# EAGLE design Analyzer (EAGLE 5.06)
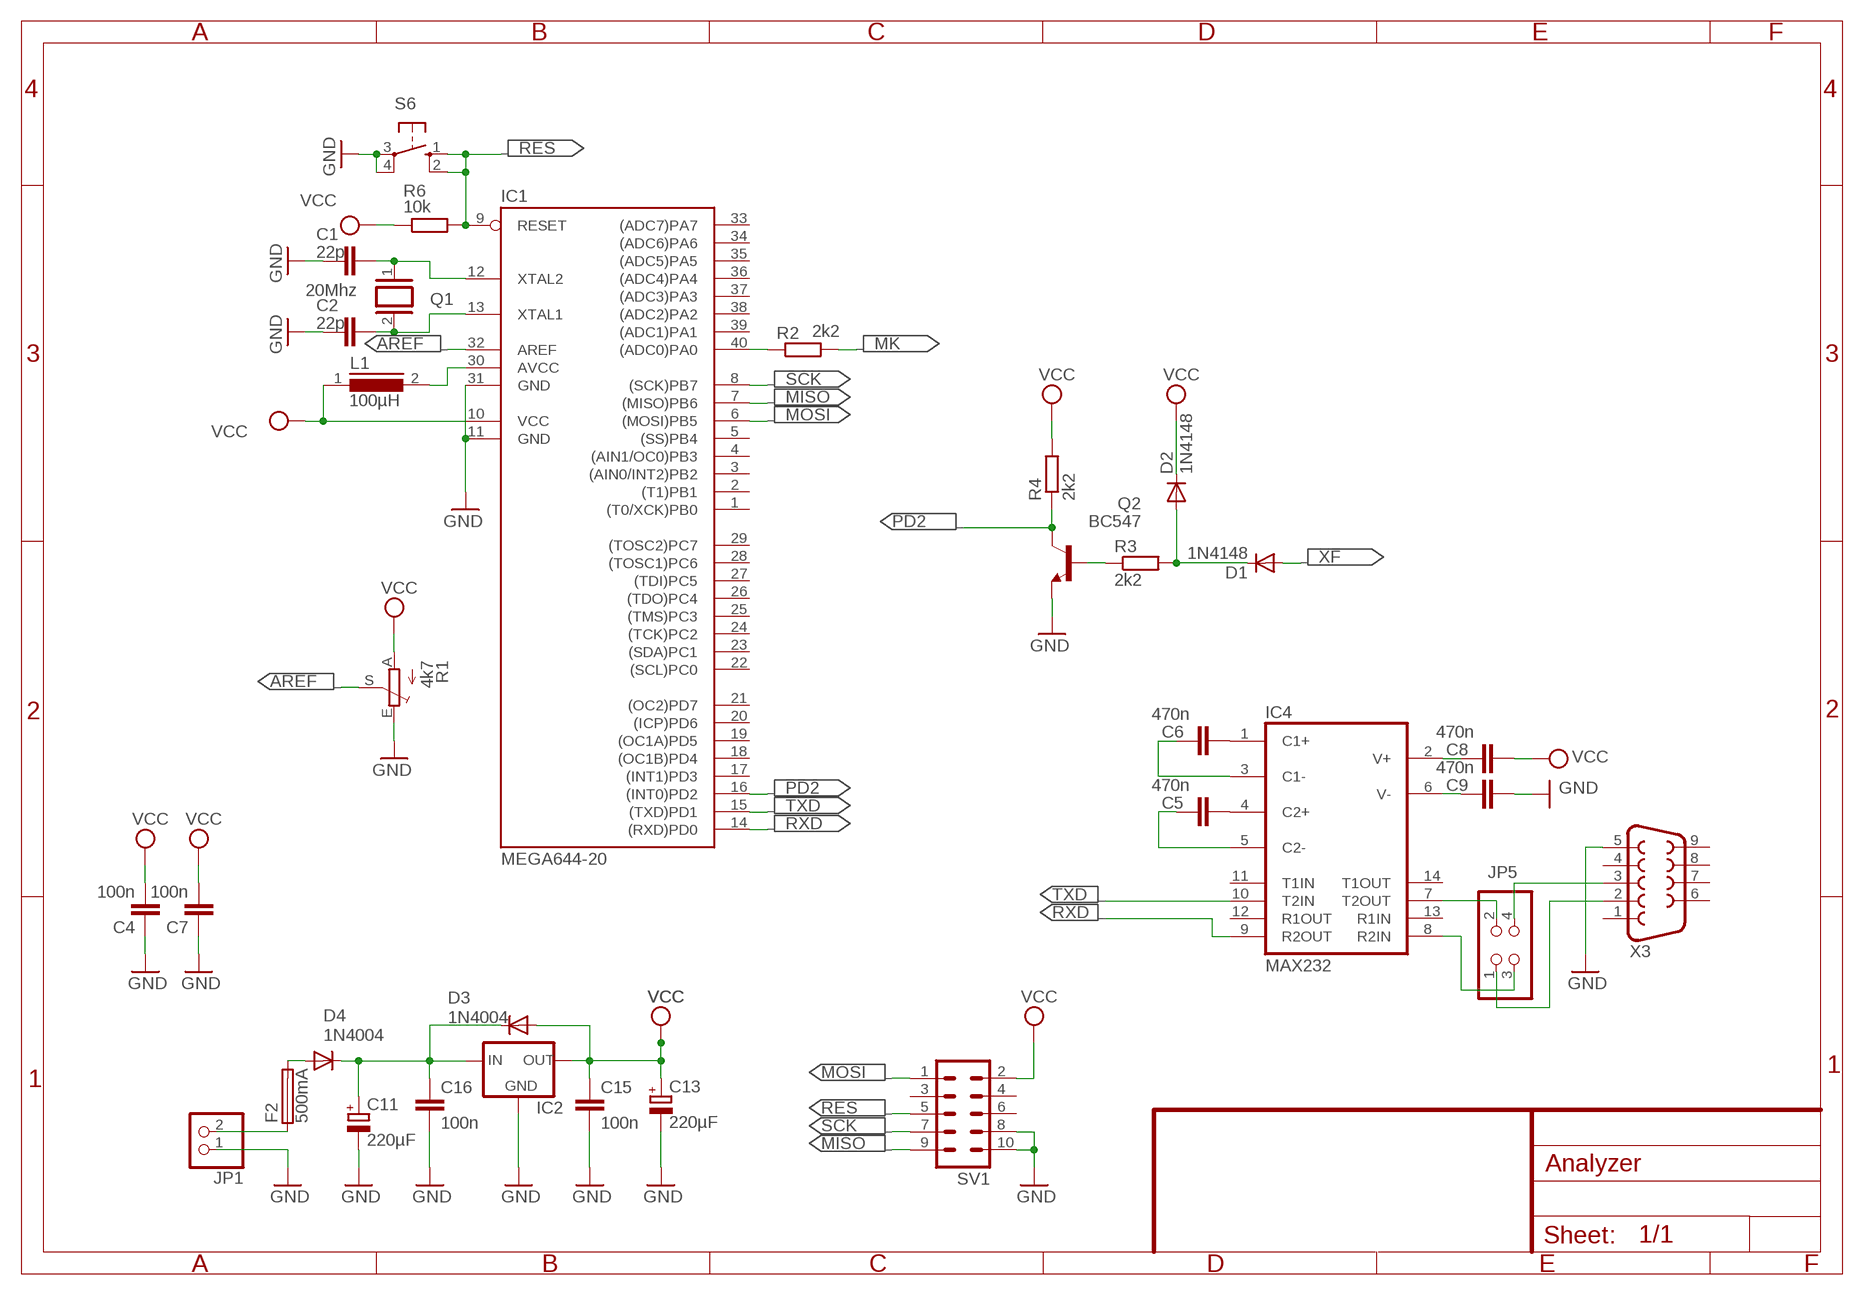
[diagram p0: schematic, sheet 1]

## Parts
C1  22p  C-EU025-024X044  [C025-024X044]
C2  22p  C-EU025-024X044  [C025-024X044]
C4  100n  C-EU025-024X044  [C025-024X044]
C5  470n  C-EU050-024X044  [C050-024X044]
C6  470n  C-EU050-024X044  [C050-024X044]
C7  100n  C-EU025-024X044  [C025-024X044]
C8  470n  C-EU050-024X044  [C050-024X044]
C9  470n  C-EU050-024X044  [C050-024X044]
C11  220µF  CPOL-EUE3.5-8  [E3,5-8]
C13  220µF  CPOL-EUE3.5-8  [E3,5-8]
C15  100n  C-EU050-024X044  [C050-024X044]
C16  100n  C-EU050-024X044  [C050-024X044]
D1  1N4148  1N4148DO35-7  [DO35-7]
D2  1N4148  1N4148DO35-7  [DO35-7]
D3  1N4004  [DO41-10]
D4  1N4004  [DO41-10]
F2  500mA  PICOFUSE  [PICOFUSE]
IC1  MEGA644-20  MEGA32-P  [DIL40]
IC2  78XXL  [78XXL]
IC4  MAX232  [DIL16]
JP1  PINHD-1X2  [1X02]
JP5  PINHD-2X2  [2X02]
L1  100µH  MCC10  [MCC10]
Q1  20Mhz  XTAL/S  [QS]
Q2  BC547  [TO92]
R1  4k7  TRIM_EU-B64W  [B64W]
R2  2k2  R-EU_0207/10  [0207/10]
R3  2k2  R-EU_0207/10  [0207/10]
R4  2k2  R-EU_0207/10  [0207/10]
R6  10k  R-EU_0207/10  [0207/10]
S6  10-XX  [B3F-10XX]
SV1  ML10  [ML10]
X3  F09HP  [F09HP]

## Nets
AREF: IC1.32(AREF) R1.S
GND: C1.1 C2.1 C4.1 C7.1 C9.2 C11.- C13.- C15.2 C16.2 IC1.11(GND) IC1.31(GND) IC2.GND JP1.1 Q2.1(E) R1.E S6.3(P) S6.4(P1) SV1.8 SV1.10 X3.5
MISO: IC1.7((MISO)PB6) SV1.9
MK: R2.2
MOSI: IC1.6((MOSI)PB5) SV1.1
N$1: IC1.30(AVCC) L1.2
N$2: JP5.4 X3.3
N$3: IC1.40((ADC0)PA0) R2.1
N$4: D1.C D2.A R3.2
N$5: Q2.2(B) R3.1
N$35: IC4.8(R2IN) JP5.3
N$36: IC4.7(T2OUT) JP5.2
N$40: JP5.1 X3.2
N$45: D4.A F2.2
N$46: F2.1 JP1.2
N$52: C5.2 IC4.4(C2+)
N$53: C5.1 IC4.5(C2-)
N$56: C6.1 IC4.3(C1-)
N$57: C6.2 IC4.1(C1+)
N$58: C8.1 IC4.2(V+)
N$59: C9.1 IC4.6(V-)
N$250: C11.+ C16.1 D3.C D4.C IC2.IN
PD2: IC1.16((INT0)PD2) Q2.3(C) R4.1
RES: IC1.9(RESET) R6.2 S6.1(S) S6.2(S1) SV1.5
RXD: IC1.14((RXD)PD0) IC4.9(R2OUT)
SCK: IC1.8((SCK)PB7) SV1.7
TXD: IC1.15((TXD)PD1) IC4.10(T2IN)
VCC: C4.2 C7.2 C8.2 C13.+ C15.1 D2.C D3.A IC1.10(VCC) IC2.OUT L1.1 R1.A R4.2 R6.1 SV1.2
XF: D1.A
XTAL1: C2.2 IC1.13(XTAL1) Q1.2
XTAL2: C1.2 IC1.12(XTAL2) Q1.1
Unconnected: IC1.1((T0/XCK)PB0) IC1.2((T1)PB1) IC1.3((AIN0/INT2)PB2) IC1.4((AIN1/OC0)PB3) IC1.5((SS)PB4) IC1.17((INT1)PD3) IC1.18((OC1B)PD4) IC1.19((OC1A)PD5) IC1.20((ICP)PD6) IC1.21((OC2)PD7) IC1.22((SCL)PC0) IC1.23((SDA)PC1) IC1.24((TCK)PC2) IC1.25((TMS)PC3) IC1.26((TDO)PC4) IC1.27((TDI)PC5) IC1.28((TOSC1)PC6) IC1.29((TOSC2)PC7) IC1.33((ADC7)PA7) IC1.34((ADC6)PA6) IC1.35((ADC5)PA5) IC1.36((ADC4)PA4) IC1.37((ADC3)PA3) IC1.38((ADC2)PA2) IC1.39((ADC1)PA1) IC4.11(T1IN) IC4.12(R1OUT) IC4.13(R1IN) IC4.14(T1OUT) SV1.3 SV1.4 SV1.6 X3.1 X3.4 X3.6 X3.7 X3.8 X3.9

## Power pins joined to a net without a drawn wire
GND: IC4.15(GND)
VCC: IC4.16(VCC)

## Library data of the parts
C1 C2 C4-C9 C15 C16 = rcl:C-EU: CAPACITOR, European symbol
C11 C13 = rcl:CPOL-EU: POLARIZED CAPACITOR, European symbol
D1 D2 = diode:1N4148: DIODE
D3 D4 = diode:1N4004: DIODE
F2 = fuse:PICOFUSE: PICOFUSE
IC1 = atmel:MEGA32-P: MICROCONTROLLER 32 Kbytes FLASH 2 Kbytes SRAM 1 Kbytes EEPROM USART 8-channel 10 bit ADC Source: www.atmel.com .. doc2503.pdf
IC2 = v-reg:78XXL: VOLTAGE REGULATOR
IC4 = maxim:MAX232: RS232 TRANSEIVER
JP1 = pinhead:PINHD-1X2: PIN HEADER
JP5 = pinhead:PINHD-2X2: PIN HEADER
L1 = inductors:MCC10: INDUCTOR
Q1 = special:XTAL/S: CRYSTAL
Q2 = transistor-npn:BC547*: NPN Transistor
R1 = pot:TRIM_EU-: POTENTIOMETER
R2-R4 R6 = rcl:R-EU_: RESISTOR, European symbol
S6 = switch-omron:10-XX: OMRON SWITCH
SV1 = con-harting-ml:ML10: HARTING
X3 = con-subd:F09: SUB-D

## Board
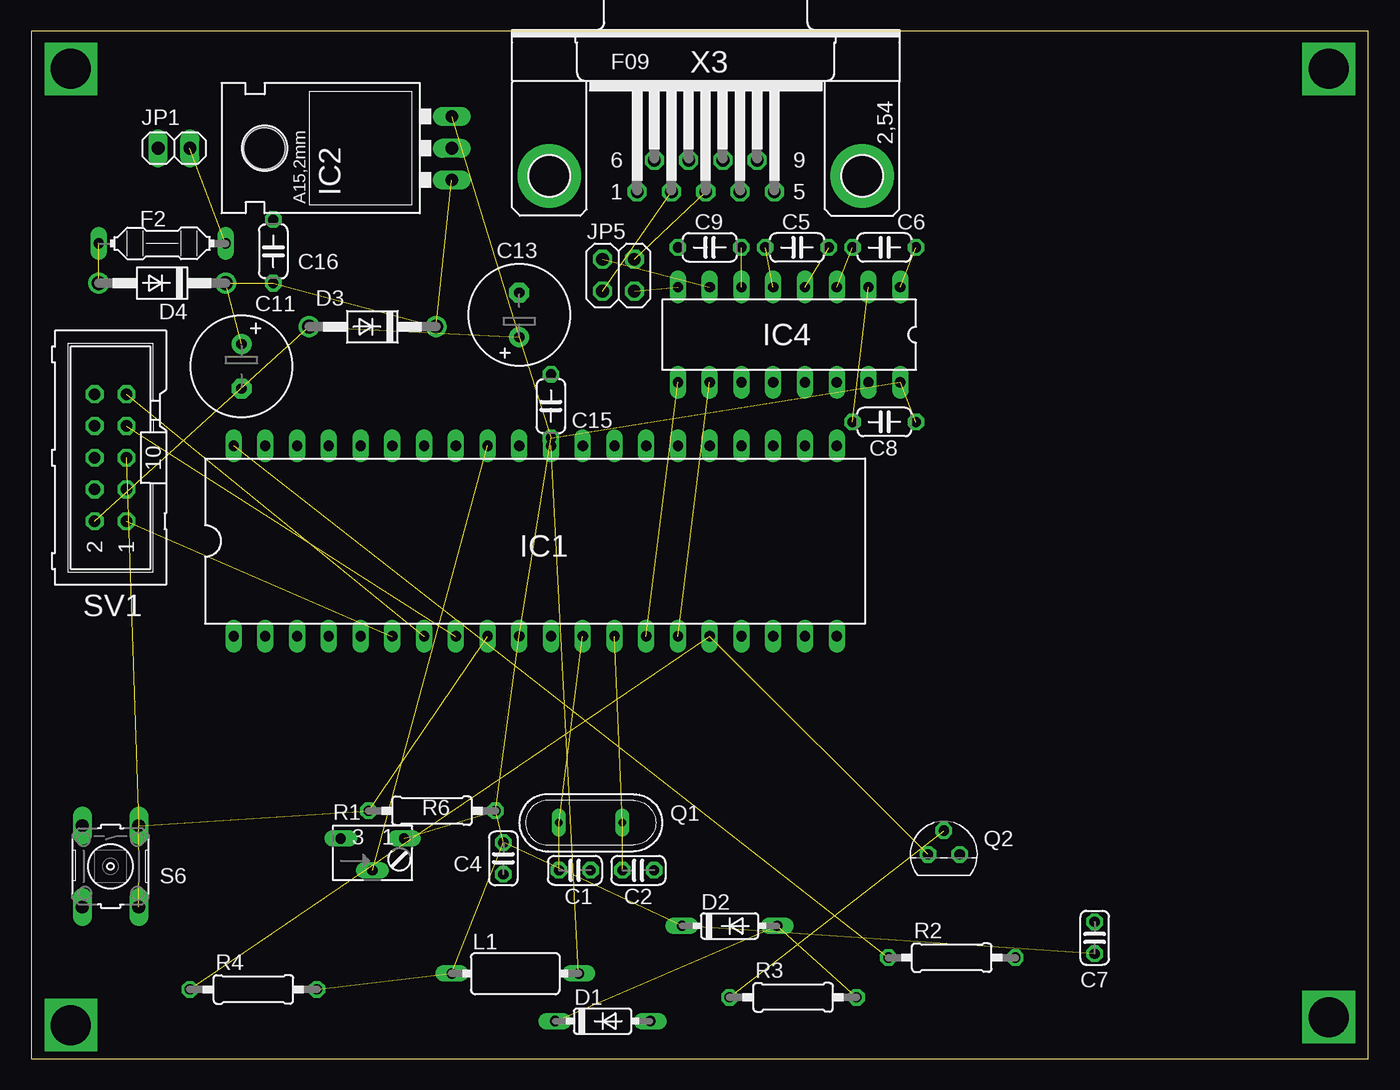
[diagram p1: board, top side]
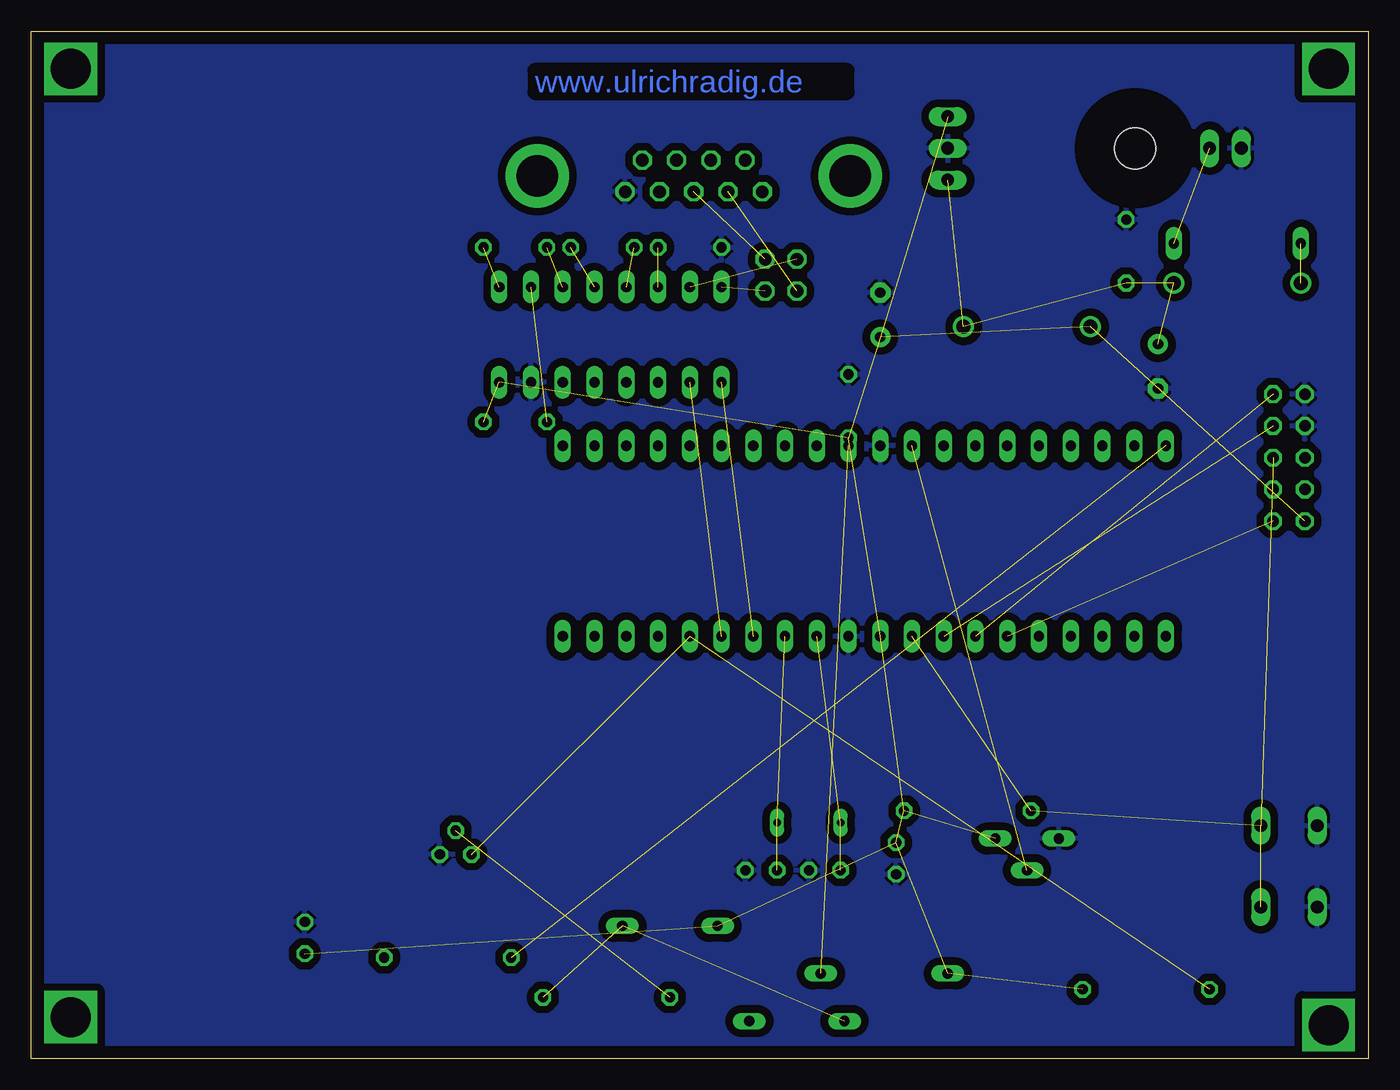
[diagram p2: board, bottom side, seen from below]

Size 106.98 x 82.22 mm. Coordinates in mm from the lower left corner, seen from the top.
Outline: 0,0 106.98,0 106.98,82.22 0,82.22 0,0
Copper layers (1*16): Top 0.035mm / dielectric 1.5mm / Bottom 0.035mm
Design rules "default": minimum track width 10mil, minimum drill 24mil, track to track 8mil, track to pad 8mil, pad to pad 8mil, via to via 8mil, smd to smd 8mil, copper to edge 40mil, drill to drill 8mil, minimum pad ring 10mil, minimum via ring 8mil, stop-mask expansion 4mil, vias tented up to drill 0mil, thermal gap 10mil

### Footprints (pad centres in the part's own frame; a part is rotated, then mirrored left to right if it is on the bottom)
C025-024X044 = drill 0.813 octagon: 1 -1.27,0; 2 1.27,0
C050-024X044 = drill 0.813 octagon: 1 -2.54,0; 2 2.54,0
E3,5-8 = drill 0.813 pad 1.6 round: + -1.778,0 | drill 0.813 pad 1.6 octagon: - 1.778,0
DO35-7 = drill 0.813 long: A 3.81,0; C -3.81,0
DO41-10 = drill 1.118 round: A 5.08,0; C -5.08,0
PICOFUSE = drill 0.813 long: 1 -5.08,0; 2 5.08,0
DIL40 = drill 0.813 long: 1 -24.13,-7.62; 2 -21.59,-7.62; 3 -19.05,-7.62; 4 -16.51,-7.62; 5 -13.97,-7.62; 6 -11.43,-7.62; 7 -8.89,-7.62; 8 -6.35,-7.62; 9 -3.81,-7.62; 10 -1.27,-7.62; 11 1.27,-7.62; 12 3.81,-7.62; 13 6.35,-7.62; 14 8.89,-7.62; 15 11.43,-7.62; 16 13.97,-7.62; 17 16.51,-7.62; 18 19.05,-7.62; 19 21.59,-7.62; 20 24.13,-7.62; 21 24.13,7.62; 22 21.59,7.62; 23 19.05,7.62; 24 16.51,7.62; 25 13.97,7.62; 26 11.43,7.62; 27 8.89,7.62; 28 6.35,7.62; 29 3.81,7.62; 30 1.27,7.62; 31 -1.27,7.62; 32 -3.81,7.62; 33 -6.35,7.62; 34 -8.89,7.62; 35 -11.43,7.62; 36 -13.97,7.62; 37 -16.51,7.62; 38 -19.05,7.62; 39 -21.59,7.62; 40 -24.13,7.62
78XXL = drill 1.016 long: GND 0,-3.81; IN -2.54,-3.81; OUT 2.54,-3.81 | hole 3.302: 0,11.176
DIL16 = drill 0.813 long: 1 -8.89,-3.81; 2 -6.35,-3.81; 3 -3.81,-3.81; 4 -1.27,-3.81; 5 1.27,-3.81; 6 3.81,-3.81; 7 6.35,-3.81; 8 8.89,-3.81; 9 8.89,3.81; 10 6.35,3.81; 11 3.81,3.81; 12 1.27,3.81; 13 -1.27,3.81; 14 -3.81,3.81; 15 -6.35,3.81; 16 -8.89,3.81
1X02 = drill 1.016 long: 1 -1.27,0; 2 1.27,0
2X02 = drill 1.016 octagon: 1 -1.27,-1.27; 2 -1.27,1.27; 3 1.27,-1.27; 4 1.27,1.27
MCC10 = drill 0.813 long: 1 -5.08,0; 2 5.08,0
QS = drill 0.61 long: 1 -2.54,0; 2 2.54,0
TO92 = drill 0.813 octagon: 1 1.27,0; 2 0,1.905; 3 -1.27,0
B64W = drill 0.813 long: A 2.54,0; E -2.54,0; S 0,-2.54
0207/10 = drill 0.813 octagon: 1 -5.08,0; 2 5.08,0
B3F-10XX = drill 1.016 long: 1 -3.251,2.261; 2 3.251,2.261; 3 -3.251,-2.261; 4 3.251,-2.261
ML10 = drill 0.914 octagon: 1 -5.08,-1.27; 2 -5.08,1.27; 3 -2.54,-1.27; 4 -2.54,1.27; 5 0,-1.27; 6 0,1.27; 7 2.54,-1.27; 8 2.54,1.27; 9 5.08,-1.27; 10 5.08,1.27
F09HP = drill 1.016 octagon: 1 -5.486,-1.27; 2 -2.743,-1.27; 3 0,-1.27; 4 2.743,-1.27; 5 5.486,-1.27; 6 -4.115,1.27; 7 -1.372,1.27; 8 1.372,1.27; 9 4.115,1.27 | drill 3.302 pad 5.08 round: G1 -12.522,0; G2 12.522,0

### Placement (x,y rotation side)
C1  43.49,15.08 180 top
C2  48.57,15.08 180 top
C4  37.78,16.03 90 top
C5  61.27,64.92 0 top
C6  68.26,64.92 0 top
C7  85.09,9.68 270 top
C8  68.26,50.95 0 top
C9  54.29,64.92 180 top
C11  16.82,55.4 270 top
C13  39.05,59.52 90 top
C15  41.59,52.22 90 top
C16  19.36,64.6 90 top
D1  45.71,3.01 0 top
D2  55.88,10.63 0 top
D3  27.3,58.57 180 top
D4  10.47,62.06 180 top
F2  10.47,65.24 180 top
IC1  40.32,41.43 0 top
IC2  29.84,72.86 90 top
IC4  60.64,57.94 180 top
JP1  11.42,72.86 0 top
JP5  46.98,62.7 0 top
L1  38.73,6.82 0 top
Q1  44.76,18.89 0 top
Q2  73.02,16.35 0 top
R1  27.3,17.62 0 top
R2  73.66,8.09 0 top
R3  60.95,4.92 0 top
R4  17.78,5.55 0 top
R6  32.06,19.84 180 top
S6  6.34,15.39 270 top
SV1  6.34,48.09 90 top
X3  53.97,70.64 0 top

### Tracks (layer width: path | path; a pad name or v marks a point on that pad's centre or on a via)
AREF  (1 unrouted)
GND
  pour Bottom (isolate 0.61): -0.01,82.07 106.99,82.38 106.99,0.15 -0.01,-0.17
MISO  (1 unrouted)
MOSI  (1 unrouted)
N$1  (1 unrouted)
N$2  (1 unrouted)
N$3  (1 unrouted)
N$4  (2 unrouted)
N$5  (1 unrouted)
N$14  (via drill 3.2)
  other vias: 3.17,79.21
N$15  (via drill 3.2)
  other vias: 3.17,2.69
N$16  (via drill 3.2)
  other vias: 103.82,3.33
N$17  (via drill 3.2)
  other vias: 103.82,79.21
N$35  (1 unrouted)
N$36  (1 unrouted)
N$40  (1 unrouted)
N$45  (1 unrouted)
N$46  (1 unrouted)
N$52  (1 unrouted)
N$53  (1 unrouted)
N$56  (1 unrouted)
N$57  (1 unrouted)
N$58  (1 unrouted)
N$59  (1 unrouted)
N$250  (4 unrouted)
PD2  (2 unrouted)
RES  (4 unrouted)
RXD  (1 unrouted)
SCK  (1 unrouted)
TXD  (1 unrouted)
VCC  (14 unrouted)
XTAL1  (2 unrouted)
XTAL2  (2 unrouted)

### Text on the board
Bottom: www.ulrichradig.de
bStop: www.ulrichradig.de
